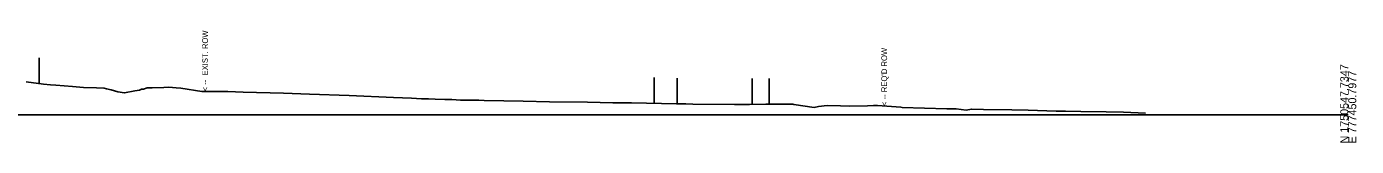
# Model space of a CAD drawing. Extents: x 776426 to 854588, y 1736205 to 1756790.
# Drawn here: x 805208.3 to 805673.6, y 1751705.1 to 1751744.3 of the extents above; entities that cross this region are included whole.
import ezdxf

# ---------------------------------------------------------------- set-up
doc = ezdxf.new("R2010")
doc.units = 0
for name, color, linetype in [('63', 7, 'Continuous'), ('DTM CONTOURS_MAJOR_TX', 7, 'Continuous'), ('DTM_X_FLOW_ARROWS', 7, 'Continuous'), ('TRANS_EOP_PAVED', 7, 'Continuous'), ('TRANS_UNPAVED_SHOULDERS', 7, 'Continuous'), ('XS_P_ROW', 7, 'Continuous'), ('XS_X_ROW', 7, 'Continuous')]:
    doc.layers.add(name, color=color, linetype=linetype)

msp = doc.modelspace()

# ---------------------------------------------------------------- linework, layer by layer
at = {"layer": '63'}
msp.add_line((805212.79, 1751734.72), (805212.79, 1751725.72), dxfattribs=at)
msp.add_line((805212.79, 1751734.72), (805212.79, 1751725.72), dxfattribs=at)
at = {"layer": 'DTM CONTOURS_MAJOR_TX'}
msp.add_line((805170.79, 1751714.76), (805670.79, 1751714.76), dxfattribs=at)
at = {"layer": 'DTM_X_FLOW_ARROWS'}
msp.add_lwpolyline([(805208.15, 1751726.25), (805214.29, 1751725.54), (805216.74, 1751725.22), (805218.53, 1751725.09), (805224.45, 1751724.65), (805228.23, 1751724.37), (805232.82, 1751724.16), (805235.52, 1751724.06), (805236.36, 1751723.85), (805237.96, 1751723.46), (805240.32, 1751722.86), (805242.55, 1751722.43), (805246.18, 1751723.13), (805247.84, 1751723.41), (805248.61, 1751723.69), (805249.27, 1751723.73), (805250.5, 1751724.16), (805252.23, 1751724.21), (805256.37, 1751724.31), (805258.14, 1751724.41), (805260.65, 1751724.24), (805262.3, 1751724.11), (805269.71, 1751722.97), (805278.72, 1751722.95), (805284.17, 1751722.73), (805298.2, 1751722.31), (805307.37, 1751721.96), (805321.25, 1751721.57), (805336.7, 1751720.87), (805343.04, 1751720.57), (805346.49, 1751720.4), (805348.99, 1751720.32), (805351.3, 1751720.25), (805354.67, 1751720.13), (805357.16, 1751720.08), (805360.22, 1751719.94), (805364.1, 1751719.9), (805366.54, 1751719.85), (805368.4, 1751719.82), (805375.32, 1751719.66), (805382.12, 1751719.49), (805391.34, 1751719.29), (805404.56, 1751719.14), (805413.48, 1751718.99), (805419.99, 1751718.93), (805435.75, 1751718.61), (805438.99, 1751718.57), (805441.4, 1751718.55), (805456.01, 1751718.42), (805458.59, 1751718.4), (805459.51, 1751718.4), (805461.34, 1751718.43), (805467.03, 1751718.49), (805476.48, 1751718.44), (805476.84, 1751718.34), (805483.88, 1751717.35), (805485.42, 1751717.63), (805488.46, 1751718.07), (805493.14, 1751717.91), (805496.17, 1751717.75), (805502.59, 1751717.94), (805504.72, 1751718.06), (805505.74, 1751718.04), (805506.11, 1751718.03), (805514.21, 1751717.39), (805514.71, 1751717.35), (805530.27, 1751716.92), (805533.6, 1751716.84), (805537.04, 1751716.35), (805538.95, 1751716.76), (805543.18, 1751716.64), (805553.09, 1751716.52), (805558.76, 1751716.44), (805568.64, 1751716.1), (805571.89, 1751716.02), (805577.21, 1751715.96), (805586.08, 1751715.79), (805592.14, 1751715.64), (805599.81, 1751715.39)], dxfattribs=at)
at = {"layer": 'TRANS_EOP_PAVED'}
for p, q in [((805436.03, 1751727.61), (805436.03, 1751718.61)), ((805436.03, 1751727.61), (805436.03, 1751718.61)), ((805462.18, 1751727.44), (805462.18, 1751718.44)), ((805462.18, 1751727.44), (805462.18, 1751718.44))]:
    msp.add_line(p, q, dxfattribs=at)
at = {"layer": 'TRANS_UNPAVED_SHOULDERS'}
for p, q in [((805427.98, 1751727.77), (805427.98, 1751718.77)), ((805427.98, 1751727.77), (805427.98, 1751718.77)), ((805468.21, 1751727.49), (805468.21, 1751718.49)), ((805468.21, 1751727.49), (805468.21, 1751718.49))]:
    msp.add_line(p, q, dxfattribs=at)

# ---------------------------------------------------------------- texts
at = {"layer": 'DTM CONTOURS_MAJOR_TX'}
for s, p in [('N 1750547.7347', (805670.79, 1751704.76)), ('E 777450.7977', (805673.59, 1751704.76))]:
    msp.add_text(s, height=2.8, rotation=90, dxfattribs=at).set_placement(p)
at = {"layer": 'XS_P_ROW'}
msp.add_text("< -- REQ'D ROW", height=2, rotation=90, dxfattribs=at).set_placement((805509.43, 1751717.85))
at = {"layer": 'XS_X_ROW'}
msp.add_text('< --  EXIST. ROW', height=2, rotation=90, dxfattribs=at).set_placement((805271.79, 1751722.96))

doc.saveas('drawing.dxf')
